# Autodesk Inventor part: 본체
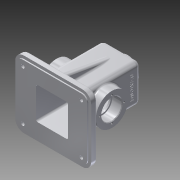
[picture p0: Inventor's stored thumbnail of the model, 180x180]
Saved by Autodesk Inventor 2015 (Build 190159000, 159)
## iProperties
Created: 2016-02
Part Number: 본체
Material: 알루미늄 6061
Document SubType Name: Modeling
Designer: Administrator
Density: 2.7 g/cm^3
Appearance: 알루미늄 - 평지
Mass: 887.337 g
Surface Area: 960.564 cm^2
Volume: 328.643 cm^3
Author: Administrator
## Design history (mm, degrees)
sketch "스케치1"
  geometry: L1 (60, 52.5)-(-60, 52.5); L2 (-60, 52.5)-(-60, -52.5); L3 (-60, -52.5)-(60, -52.5); L4 (60, -52.5)-(60, 52.5); L5 (60, 52.5)-(-60, -52.5); L6 (-60, 52.5)-(60, -52.5); 1 further point
  constraints: 12 end point, 2 midpoint, 2 parallel, 1 horizontal, 1 perpendicular
  dimensions: "d0" = 120 distance of L3.end L2.end; "d1" = 105 distance of L2.end L1.end
extrude "돌출1" new body sketch "스케치1" distance "d2" = 2; taper "d3" = 0 deg
sketch "스케치2"
  geometry: L1 (65, -57.5)-(-65, -57.5); L2 (-65, -57.5)-(-65, 57.5); L3 (-65, 57.5)-(65, 57.5); L4 (65, 57.5)-(65, -57.5); L5 (65, -57.5)-(-65, 57.5); L6 (-65, -57.5)-(65, 57.5); 1 further point
  constraints: 12 end point, 2 midpoint, 2 parallel, 1 horizontal, 1 perpendicular
  dimensions: "d4" = 130 distance of L2.end L3.end; "d5" = 115 distance of L1.end L2.end
extrude "돌출2" join sketch "스케치2" distance "d6" = 10; taper "d7" = 0 deg
sketch "스케치3"
  geometry: L1 (60, 52.5)-(60, -52.5) reference; L2 (60, -52.5)-(-60, -52.5) reference; L3 (-60, -52.5)-(-60, 52.5) reference; L4 (-60, 52.5)-(60, 52.5) reference; L5 (32.5, 32.5)-(-32.5, 32.5); L6 (-32.5, 32.5)-(-32.5, -32.5); L7 (-32.5, -32.5)-(32.5, -32.5); L8 (32.5, -32.5)-(32.5, 32.5); L9 (32.5, 32.5)-(-32.5, -32.5); L10 (-32.5, 32.5)-(32.5, -32.5); 1 further point
  constraints: 12 end point, 2 midpoint, 2 parallel, 1 horizontal, 1 perpendicular
  dimensions: "d8" = 65 distance of L7.end L6.end; "d9" = 65 distance of L6.end L5.end
extrude "돌출3" join sketch "스케치3" distance "d10" = 120; taper "d11" = 0 deg
sketch "스케치4"
  geometry: L1 (2, 52.5)-(2, 57.5) reference; L2 (2, 57.5)-(12, 57.5) reference; L3 (12, 57.5)-(12, 32.5) reference; L4 (12, 32.5)-(120, 32.5) reference; L5 (120, 32.5)-(120, -32.5) reference; L6 (120, -32.5)-(12, -32.5) reference; L7 (12, -32.5)-(12, -57.5) reference; L8 (12, -57.5)-(2, -57.5) reference; L9 (2, -57.5)-(2, -52.5) reference; L10 (2, -52.5)-(0, -52.5) reference; L11 (0, -52.5)-(0, 52.5) reference; L12 (0, 52.5)-(2, 52.5) reference; L13 (55, -32.5)-(55, 32.5); C1 r 27.5 at (55, 0); 2 further points
  constraints: 2 end point, 2 midpoint, 2 point on line, 1 centre point, 1 horizontal alignment, 1 vertical
  dimensions: "d12" = 55 distance between parallel lines of L11 L13; "d13" = 55 diameter of C1
extrude "돌출4" join sketch "스케치4" stored distance "d14" = 95; taper "d15" = 0 deg
sketch "스케치5"
  geometry: C1 r 20 at (0, 0); 1 further point
  constraints: 1 centre point, 1 coincident
  dimensions: "d16" = 40 diameter of C1
extrude "돌출5" join sketch "스케치5" distance "d17" = 10; taper "d18" = 0 deg
sketch "스케치7"
  geometry: L1 (2, 52.5)-(2, 57.5) reference; L2 (2, 57.5)-(12, 57.5) reference; L3 (12, 57.5)-(12, 32.5) reference; L4 (12, 32.5)-(120, 32.5) reference; L5 (120, 32.5)-(120, 20) reference; L6 (120, 20)-(130, 20) reference; L7 (130, 20)-(130, -20) reference; L8 (130, -20)-(120, -20) reference; L9 (120, -20)-(120, -32.5) reference; L10 (120, -32.5)-(12, -32.5) reference; L11 (12, -32.5)-(12, -57.5) reference; L12 (12, -57.5)-(2, -57.5) reference; L13 (2, -57.5)-(2, -52.5) reference; L14 (2, -52.5)-(0, -52.5) reference; L15 (0, -52.5)-(0, 52.5) reference; L16 (0, 52.5)-(2, 52.5) reference; L17 (97.069, 32.5)-(12, 47.5); L18 (12, -57.5)-(12, 57.5) reference; L19 (97.069, 32.5)-(97.069, -32.5); L20 (12, -32.5)-(120, -32.5) reference; L21 (97.069, -32.5)-(12, -47.5); L22 (12, 47.5)-(12, -47.5); 1 further point
  constraints: 8 end point, 4 point on line, 1 collinear, 1 perpendicular
  dimensions: "d22" = 10 deg angle of L17 L2; "d23" = 10 deg angle of L12 L21; "d24" = 10 distance of L11.end L21.end
extrude "돌출6" join sketch "스케치7" stored distance "d25" = 10; taper "d26" = 0 deg
hole "구멍1" diameter "d32" = 35; stored, may be unused: countersink angle "d36" = 90 deg, drill point angle "d38" = 0 deg; dims "d33" = 6, "d34" = 4, "d35" = 2, "d37" = 17, "d144" = 10, "d145" = 10
hole "구멍2" diameter "d41" = 21; stored, may be unused: countersink angle "d45" = 90 deg, drill point angle "d47" = 118 deg; dims "d39" = 10, "d40" = 10, "d42" = 6, "d43" = 4, "d44" = 2, "d46" = 8
fillet "모깎기1" dims "d48" = 15
fillet "모깎기2" dims "d49" = 8
feature "면 기울기1" dims angle "d50" = 5 deg
fillet "모깎기3" dims "d51" = 8
sketch "스케치9"
  geometry: L1 (-49, 0)-(0, 0) reference; L2 (-27.5, 0)-(-21.5, 0); L3 (-21.5, 0)-(-21.5, 18); L4 (-21.5, 18)-(-27.5, 18); L5 (-27.5, 18)-(-27.5, 0); A1 r 27.5 centre (-24.5, 43) between (-49, 30.51) and (0, 30.51) reference; 1 further point
  constraints: 8 end point, 2 parallel, 1 horizontal, 1 perpendicular, 1 point on line
  dimensions: "d52" = 6 distance of L4.end L3.end; "d53" = 3 distance from line of L3 A1.centre; "d54" = 18 distance of L2.end L3.end
extrude "돌출7" join sketch "스케치9" distance "d55" = 10; taper "d56" = 0 deg
sketch "스케치10"
  geometry: L1 (-5, -32.5)-(-24.5, -32.5) reference; L2 (-32.5, -24.5)-(-32.5, -3) reference; L3 (-32.5, -3)-(-42.5, -3) reference; L4 (-42.5, -3)-(-42.5, 3) reference; L5 (-42.5, 3)-(-32.5, 3) reference; L6 (-32.5, 3)-(-32.5, 24.5) reference; L7 (-24.5, 32.5)-(-5, 32.5) reference; L8 (-5, 32.5)-(-5, 47.5) reference; L9 (-5, 47.5)-(5, 47.5) reference; L10 (5, 47.5)-(5, 32.5) reference; L11 (5, 32.5)-(24.5, 32.5) reference; L12 (32.5, 24.5)-(32.5, 3) reference; L13 (32.5, 3)-(42.5, 3) reference; L14 (42.5, 3)-(42.5, -3) reference; L15 (42.5, -3)-(32.5, -3) reference; L16 (32.5, -3)-(32.5, -24.5) reference; L17 (24.5, -32.5)-(5, -32.5) reference; L18 (5, -32.5)-(5, -47.5) reference; L19 (5, -47.5)-(-5, -47.5) reference; L20 (-5, -47.5)-(-5, -32.5) reference; L21 (65, 42.5)-(65, -42.5) reference; L22 (50, -57.5)-(-50, -57.5) reference; L23 (-65, -42.5)-(-65, 42.5) reference; L24 (-50, 57.5)-(50, 57.5) reference; C1 r 7.5 at (50, 42.5); C2 r 7.5 at (50, -42.5); C3 r 7.5 at (-50, -42.5); C4 r 7.5 at (-50, 42.5); C5 r 10.5 at (0, 0) reference; A1 r 8 centre (-24.5, -24.5) between (-32.5, -24.5) and (-24.5, -32.5) reference; A2 r 8 centre (-24.5, 24.5) between (-24.5, 32.5) and (-32.5, 24.5) reference; A3 r 8 centre (24.5, 24.5) between (32.5, 24.5) and (24.5, 32.5) reference; A4 r 8 centre (24.5, -24.5) between (24.5, -32.5) and (32.5, -24.5) reference; A5 r 15 centre (50, 42.5) between (65, 42.5) and (50, 57.5) reference; A6 r 15 centre (50, -42.5) between (50, -57.5) and (65, -42.5) reference; A7 r 15 centre (-50, -42.5) between (-65, -42.5) and (-50, -57.5) reference; A8 r 15 centre (-50, 42.5) between (-50, 57.5) and (-65, 42.5) reference; 1 further point
  constraints: 4 centre point, 4 coincident, 3 equal radius
  dimensions: "d57" = 15 diameter of C1
extrude "돌출8" join sketch "스케치10" distance "d58" = 3; taper "d59" = 0 deg
hole "구멍3" diameter "d62" = 6; stored, may be unused: countersink angle "d66" = 90 deg, drill point angle "d68" = 118 deg; dims "d60" = 10, "d61" = 10, "d63" = 6, "d64" = 4, "d65" = 2, "d67" = 8
hole "구멍4" diameter "d71" = 6; stored, may be unused: countersink angle "d75" = 90 deg, drill point angle "d77" = 118 deg; dims "d69" = 10, "d70" = 10, "d72" = 6, "d73" = 4, "d74" = 2, "d76" = 8
hole "구멍5" diameter "d80" = 6; stored, may be unused: countersink angle "d84" = 90 deg, drill point angle "d86" = 118 deg; dims "d78" = 10, "d79" = 10, "d81" = 6, "d82" = 4, "d83" = 2, "d85" = 8
hole "구멍6" diameter "d89" = 6; stored, may be unused: countersink angle "d93" = 90 deg, drill point angle "d95" = 118 deg; dims "d87" = 10, "d88" = 10, "d90" = 6, "d91" = 4, "d92" = 2, "d94" = 8
sketch "스케치11" dims "d96" = 29
  geometry: C1 r 10.5 at (0, 0) reference; C2 r 19.125 at (0, 0) reference; 2 further points
  constraints: 2 vertical alignment, 1 coincident, 2 other
hole "구멍7" sketch "스케치11" at (0, 14.5) diameter "d97" = 2.459; stored, may be unused: countersink angle "d101" = 90 deg, drill point angle "d103" = 118 deg; dims "d98" = 7, "d99" = 4, "d100" = 2, "d102" = 9
sketch "스케치12" dims "d104" = 42
  geometry: C1 r 17.5 at (0, 0) reference; C2 r 27.5 at (0, 0) reference; 3 further points
  constraints: 2 vertical alignment, 1 coincident, 2 other
hole "구멍8" sketch "스케치12" at (0, 21) diameter "d105" = 3.242; stored, may be unused: countersink angle "d109" = 90 deg, drill point angle "d111" = 118 deg; dims "d106" = 8, "d107" = 4, "d108" = 2, "d110" = 10
node "작업 평면1"
sketch "스케치13"
  geometry: L1 (-32.5, 57)-(-32.5, -43) reference; L2 (24.5, 65)-(-24.5, 65) reference; L3 (32.5, -43)-(32.5, 57) reference; L4 (19.125, 75)-(-19.125, 75) reference; 2 further points
  constraints: 1 other
  dimensions: "d119" = 32.5 distance from line of L1 point (0, 49); "d179" = 26 distance from line of L4 point (0, 49)
feature "엠보싱1" sketch "스케치13" dims "d121" = 0.5, "d122" = 0
chamfer "모따기1" distance "d123" = 1; stored, may be unused: second distance "d124" = 2, angle "d125" = 45 deg
chamfer "모따기2" distance "d126" = 1; stored, may be unused: second distance "d127" = 2, angle "d128" = 45 deg
fillet "모깎기4" dims "d132" = 3
fillet "모깎기5" dims "d133" = 3
fillet "모깎기6" dims "d134" = 3
fillet "모깎기7" dims "d135" = 3
fillet "모깎기8" dims "d136" = 3
fillet "모깎기9" dims "d137" = 3
fillet "모깎기10" dims "d138" = 3
fillet "모깎기11" dims "d139" = 3
fillet "모깎기12" dims "d140" = 3
fillet "모깎기13" dims "d141" = 3
fillet "모깎기14" dims "d142" = 3
fillet "모깎기15" dims "d143" = 1
hole "구멍9" diameter "d148" = 35; stored, may be unused: countersink angle "d152" = 90 deg, drill point angle "d154" = 0 deg; dims "d146" = 10, "d147" = 10, "d149" = 8, "d150" = 4, "d151" = 2, "d153" = 17
hole "구멍10" diameter "d157" = 30; stored, may be unused: countersink angle "d161" = 90 deg, drill point angle "d163" = 0 deg; dims "d155" = 10, "d156" = 10, "d158" = 8, "d159" = 4, "d160" = 2, "d162" = 17
fillet "모깎기16" dims "d164" = 0.3
chamfer "모따기4" distance "d165" = 1; stored, may be unused: second distance "d166" = 2, angle "d167" = 45 deg
fillet "모깎기17" dims "d168" = 10
sketch "스케치14"
  geometry: L1 (27.5, -27.5)-(-27.5, -27.5); L2 (-27.5, -27.5)-(-27.5, 27.5); L3 (-27.5, 27.5)-(27.5, 27.5); L4 (27.5, 27.5)-(27.5, -27.5); L5 (27.5, -27.5)-(-27.5, 27.5); L6 (-27.5, -27.5)-(27.5, 27.5); C1 r 10.5 at (0, 0) reference
  constraints: 12 end point, 2 parallel, 1 horizontal, 1 perpendicular
  dimensions: "d169" = 55 distance of L2.end L3.end; "d170" = 55 distance of L1.end L2.end; "d173" = 27.5 distance from line of L3 C1.centre; "d174" = 27.5 distance from line of L2 C1.centre
extrude "돌출10" cut sketch "스케치14" distance "d175" = 115; taper "d176" = 0 deg
fillet "모깎기18" dims "d177" = 3
fillet "모깎기19" dims "d178" = 3
node "솔리드1"
mirror "대칭1"
pattern_circular "원형 패턴1" dims angle "d113" = 360 deg
pattern_circular "원형 패턴2" dims angle "d116" = 360 deg
mirror "대칭2"
node "절단 모서리 투영1"
node "절단 모서리 투영2"
node "절단 모서리 투영4"
node "절단 모서리 투영6"
other parameters: "d118" = 22.5
